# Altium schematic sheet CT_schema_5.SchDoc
size 512 x 457 mm
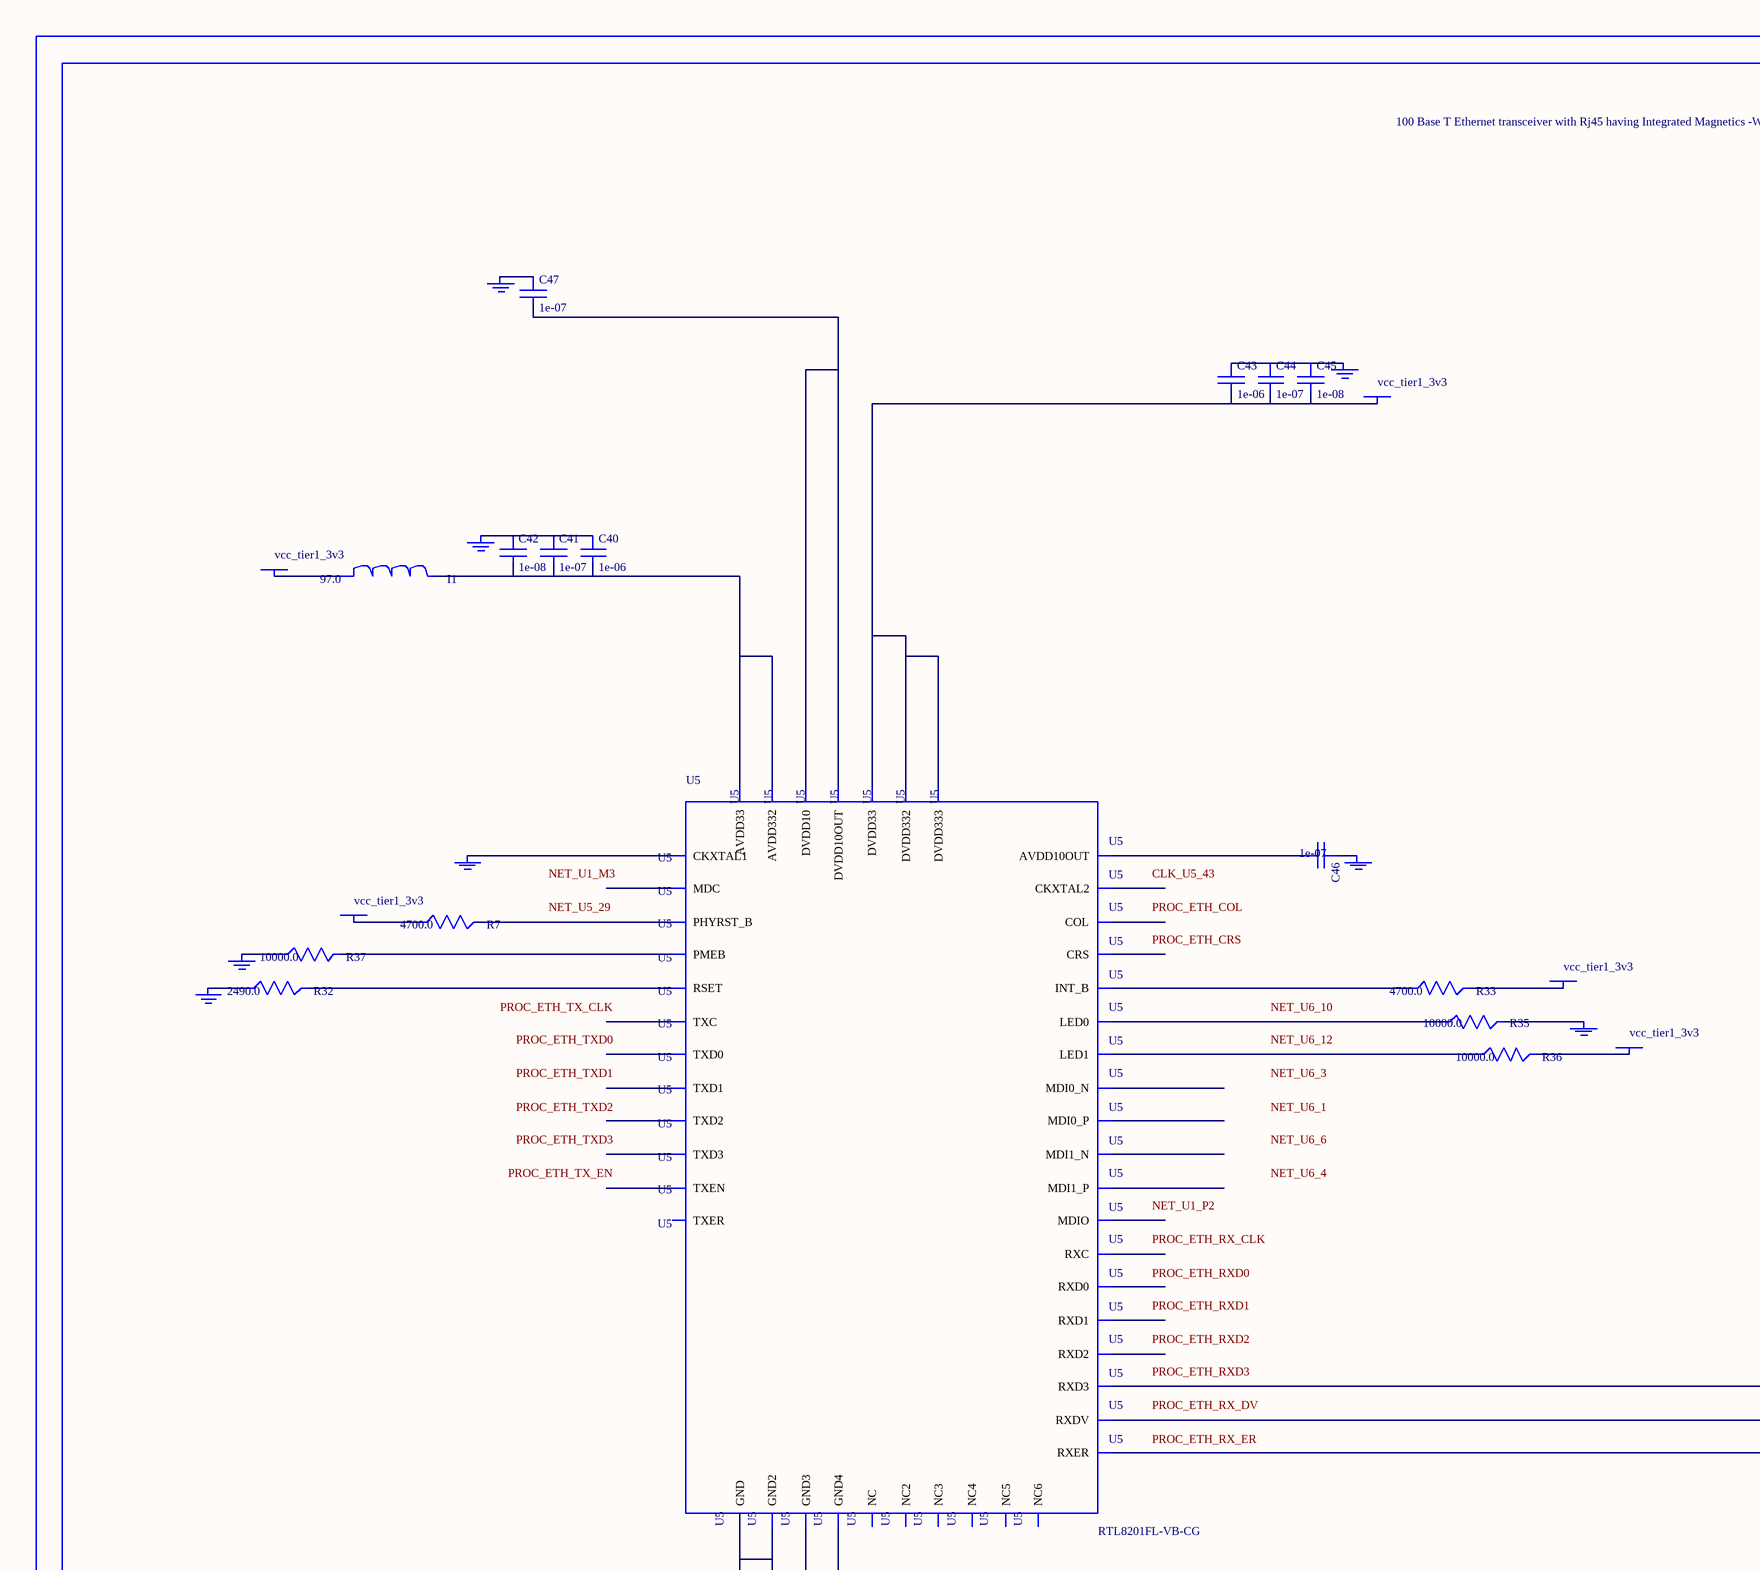
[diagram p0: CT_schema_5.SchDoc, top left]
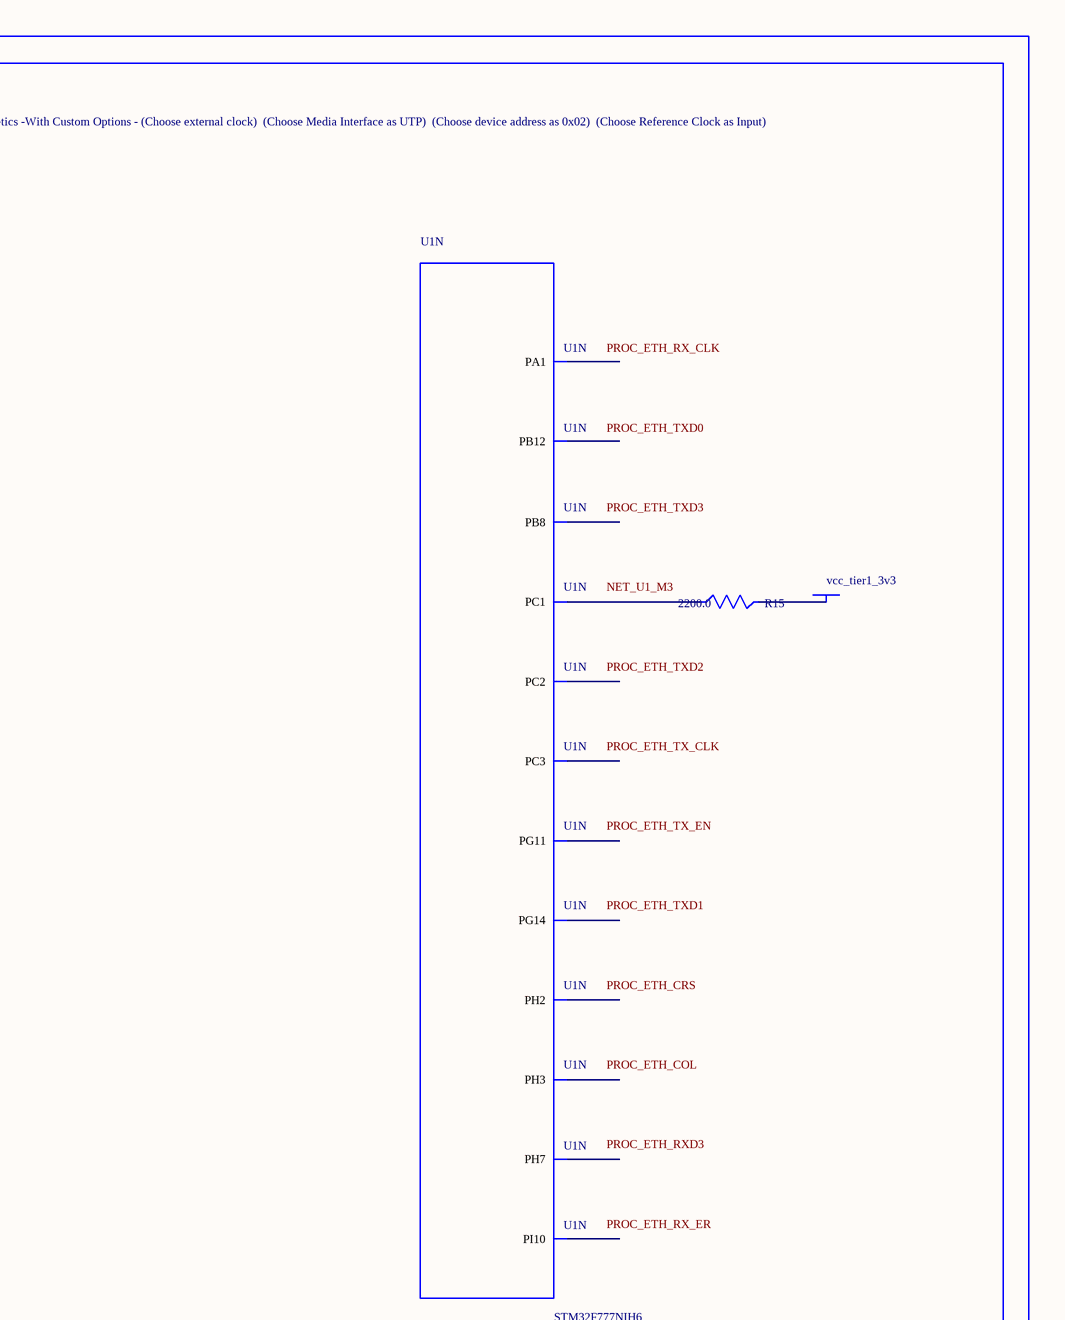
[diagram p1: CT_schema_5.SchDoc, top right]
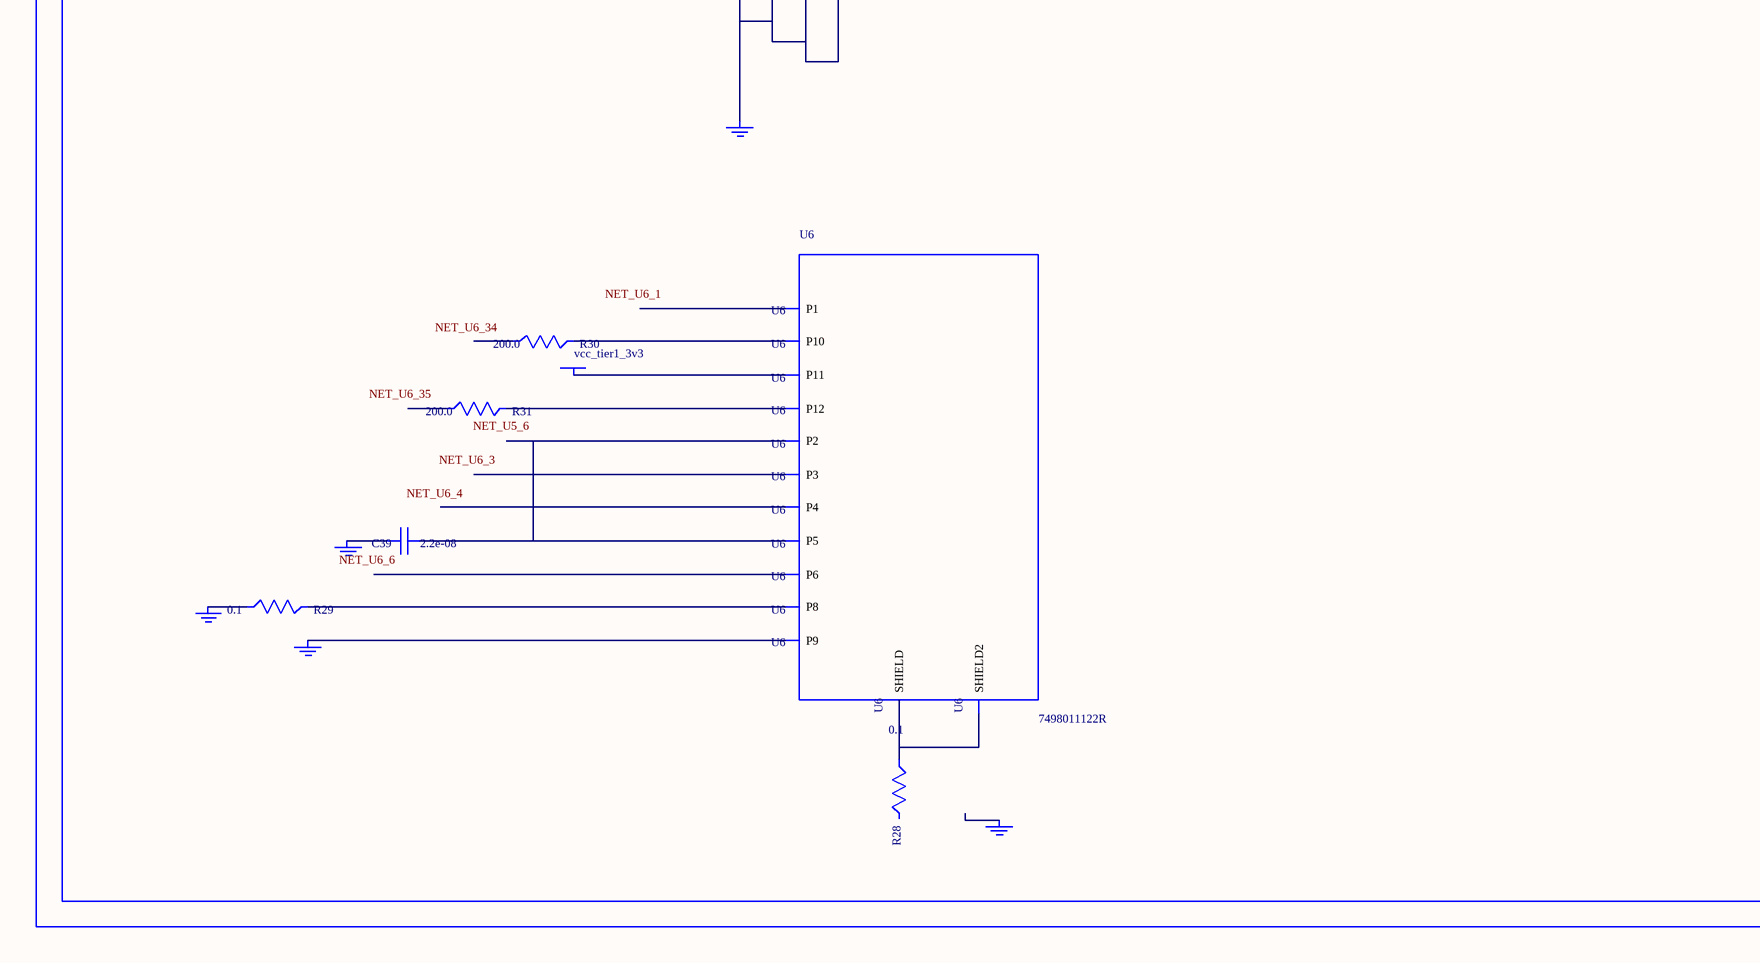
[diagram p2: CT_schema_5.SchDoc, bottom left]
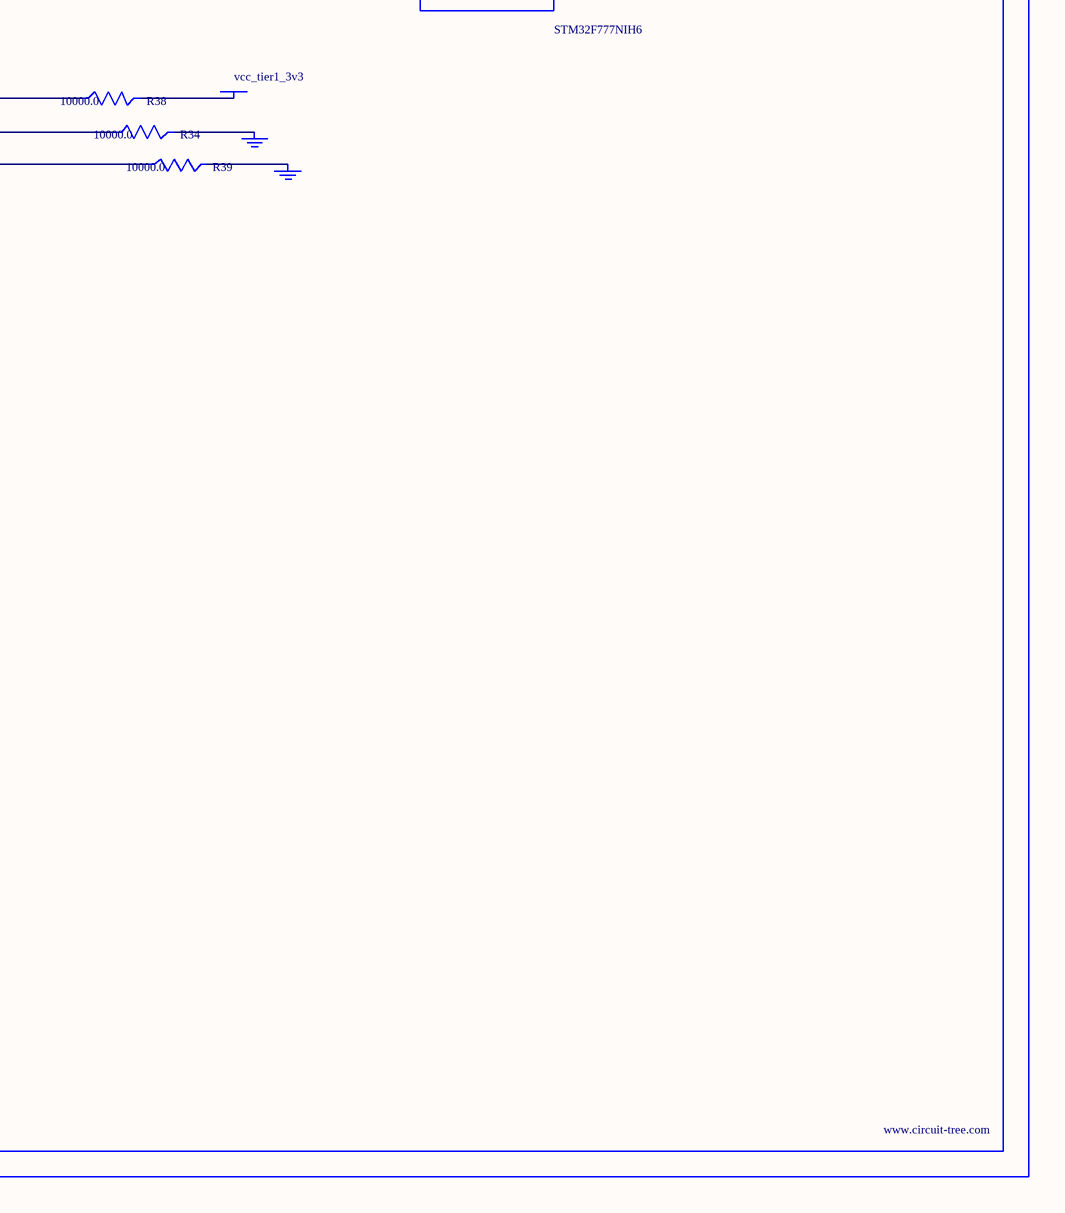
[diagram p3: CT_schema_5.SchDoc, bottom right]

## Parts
BORDER4  (no value)
C39  2.2e-08  [C0402]
C40  1e-06  [C0603]
C41  1e-07  [C0402]
C42  1e-08  [C0402]
C43  1e-06  [C0603]
C44  1e-07  [C0402]
C45  1e-08  [C0402]
C46  1e-07  [C0402]
C47  1e-07  [C0402]
GND_INSTANCE_4_0  (no value)
GND_INSTANCE_4_1  (no value)
GND_INSTANCE_4_2  (no value)
GND_INSTANCE_4_3  (no value)
GND_INSTANCE_4_4  (no value)
GND_INSTANCE_4_5  (no value)
GND_INSTANCE_4_6  (no value)
GND_INSTANCE_4_7  (no value)
GND_INSTANCE_4_8  (no value)
GND_INSTANCE_4_9  (no value)
GND_INSTANCE_4_10  (no value)
GND_INSTANCE_4_11  (no value)
GND_INSTANCE_4_12  (no value)
GND_INSTANCE_4_13  (no value)
GND_INSTANCE_4_14  (no value)
I1  97.0  [R0603]
POWER_INSTANCE_4_0  vcc_tier1_3v3
POWER_INSTANCE_4_1  vcc_tier1_3v3
POWER_INSTANCE_4_2  vcc_tier1_3v3
POWER_INSTANCE_4_3  vcc_tier1_3v3
POWER_INSTANCE_4_4  vcc_tier1_3v3
POWER_INSTANCE_4_5  vcc_tier1_3v3
POWER_INSTANCE_4_6  vcc_tier1_3v3
POWER_INSTANCE_4_7  vcc_tier1_3v3
R7  4700.0  [R0603]
R15  2200.0  [R0603]
R28  0.1  [R0603]
R29  0.1  [R0603]
R30  200.0  [R0603]
R31  200.0  [R0603]
R32  2490.0  [R0603]
R33  4700.0  [R0603]
R34  10000.0  [R0603]
R35  10000.0  [R0603]
R36  10000.0  [R0603]
R37  10000.0  [R0603]
R38  10000.0  [R0603]
R39  10000.0  [R0603]
U1  STM32F777NIH6  [TFBGA216]  (part N of 15)
U5  RTL8201FL-VB-CG  [RTL8201FL-VB-CG]
U6  7498011122R  [7498011122R]

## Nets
NetC39_1: C39.1 U6.2(P2) U6.5(P5)
NetC39_2: C39.2 GND_INSTANCE_4_11.0(GND)
NetC40_1: C40.1 C41.1 C42.1 GND_INSTANCE_4_0.0(GND)
NetC40_2: C40.2 C41.2 C42.2 I1.2 U5.6(AVDD33) U5.41(AVDD332)
NetC43_1: C43.1 C44.1 C45.1 GND_INSTANCE_4_3.0(GND)
NetC43_2: C43.2 C44.2 C45.2 POWER_INSTANCE_4_1.0(PWR) U5.15(DVDD33) U5.21(DVDD332) U5.37(DVDD333)
NetC46_1: C46.1 GND_INSTANCE_4_9.0(GND)
NetC46_2: C46.2 U5.48(AVDD10OUT)
NetC47_1: C47.1 GND_INSTANCE_4_6.0(GND)
NetC47_2: C47.2 U5.28(DVDD10) U5.40(DVDD10OUT)
NetGND_INSTANCE_4_1_0: GND_INSTANCE_4_1.0(GND) R37.1
NetGND_INSTANCE_4_2_0: GND_INSTANCE_4_2.0(GND) R34.2
NetGND_INSTANCE_4_4_0: GND_INSTANCE_4_4.0(GND) R35.2
NetGND_INSTANCE_4_5_0: GND_INSTANCE_4_5.0(GND) R39.2
NetGND_INSTANCE_4_7_0: GND_INSTANCE_4_7.0(GND) U5.42(CKXTAL1)
NetGND_INSTANCE_4_8_0: GND_INSTANCE_4_8.0(GND) R32.1
NetGND_INSTANCE_4_10_0: GND_INSTANCE_4_10.0(GND) U5.7(GND) U5.20(GND2) U5.33(GND3) U5.47(GND4)
NetGND_INSTANCE_4_12_0: GND_INSTANCE_4_12.0(GND) R29.1
NetGND_INSTANCE_4_13_0: GND_INSTANCE_4_13.0(GND) U6.9(P9)
NetI1_1: I1.1 POWER_INSTANCE_4_0.0(PWR)
NetPOWER_INSTANCE_4_2_0: POWER_INSTANCE_4_2.0(PWR) R38.2
NetPOWER_INSTANCE_4_3_0: POWER_INSTANCE_4_3.0(PWR) R33.2
NetPOWER_INSTANCE_4_4_0: POWER_INSTANCE_4_4.0(PWR) R36.2
NetPOWER_INSTANCE_4_5_0: POWER_INSTANCE_4_5.0(PWR) R7.1
NetPOWER_INSTANCE_4_6_0: POWER_INSTANCE_4_6.0(PWR) R15.2
NetPOWER_INSTANCE_4_7_0: POWER_INSTANCE_4_7.0(PWR) U6.11(P11)
NetR7_2: R7.2 U5.29(PHYRST_B)
NetR15_1: R15.1 U1.M3(PC1)
NetR28_1: R28.1 U6.13(SHIELD) U6.14(SHIELD2)
NetR29_2: R29.2 U6.8(P8)
NetR30_2: R30.2 U6.10(P10)
NetR31_2: R31.2 U6.12(P12)
NetR32_2: R32.2 U5.46(RSET)
NetR33_1: R33.1 U5.32(INT_B)
NetR34_1: R34.1 U5.13(RXDV)
NetR35_1: R35.1 U5.34(LED0)
NetR36_1: R36.1 U5.35(LED1)
NetR37_2: R37.2 U5.10(PMEB)
NetR38_1: R38.1 U5.18(RXD3)
NetR39_1: R39.1 U5.39(RXER)

Not connected (* = marked no-connect by the designer): GND_INSTANCE_4_14 0(GND); R28 2; R30 1; R31 1; U1 A4(PG14) A7(PB8) B8(PG11) D5(PI10) J4(PH3) K4(PH2) L4(PC3) L13(PB12) M4(PC2) N2(PA1) N13(PH7); U5 1(MDI0_P) 2(MDI0_N) 3(NC) 4(MDI1_P) 5(MDI1_N) 8(NC2) 9(NC3) 11(NC4) 12(TXER) 14(RXD0) 16(RXD1) 17(RXD2) 19(RXC) 22(TXC) 23(TXD0) 24(TXD1) 25(TXD2) 26(TXD3) 27(TXEN) 30(MDC) 31(MDIO) 36(CRS) 38(COL) 43(CKXTAL2) 44(NC5) 45(NC6); U6 1(P1) 3(P3) 4(P4) 6(P6)

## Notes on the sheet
- Labels drawn without touching a wire or pin: CLK_U5_43, NET_U1_M3, NET_U1_P2, NET_U5_6, NET_U5_29, NET_U6_1, NET_U6_3, NET_U6_4, NET_U6_6, NET_U6_10, NET_U6_12, NET_U6_34, NET_U6_35, PROC_ETH_COL, PROC_ETH_CRS, PROC_ETH_RX_CLK, PROC_ETH_RX_DV, PROC_ETH_RX_ER, PROC_ETH_RXD0, PROC_ETH_RXD1, PROC_ETH_RXD2, PROC_ETH_RXD3, PROC_ETH_TX_CLK, PROC_ETH_TX_EN, PROC_ETH_TXD0, PROC_ETH_TXD1, PROC_ETH_TXD2, PROC_ETH_TXD3

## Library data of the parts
BORDER4 = BORDER_PAGE4
C39 = C0402C223K3RAC
C40 C43 = C0603C105K3RACTU
C41 C44 C46 C47 = C0402C104K3RACTU
C42 C45 = C0402C103K3RAC
GND_INSTANCE_4_0-GND_INSTANCE_4_14 = GND
I1 = I1
POWER_INSTANCE_4_0-POWER_INSTANCE_4_7 = PWR
R7 R33 = RC0603JR-074K7L
R15 = RC0603JR-072K2L
R28 R29 = ERJ-3RSFR10V
R30 R31 = RC0603JR-07200RL
R32 = ERA-3AED2490V
R34-R39 = RC0603JR-0710KL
